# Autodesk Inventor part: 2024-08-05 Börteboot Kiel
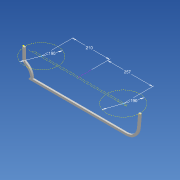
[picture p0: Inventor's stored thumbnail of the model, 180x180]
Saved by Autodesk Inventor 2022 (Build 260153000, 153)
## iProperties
Created: 2024-08
Part Number: 2024-08-05 Börteboot Kiel
Material: Generisch
Document SubType Name: Modeling
Designer: i3meg
Density: 1 g/cm^3
Appearance: Vorgabe
Author: i3meg
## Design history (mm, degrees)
sketch "Skizze3"
  geometry: L1 (0, 65)-(0, 145); L2 (45, 0)-(590, 0); L3 (-177.152, 0)-(845.976, 0) reference; L4 (0, -76.111)-(0, 353.434) reference; L5 (-13.298, 65)-(13.298, 65); L6 (45, 6.802)-(45, -6.802); L7 (649.229, 70)-(679.411, 70); L8 (590, 31.664)-(590, 6.805); L9 (664.371, 70)-(670.933, 145); L10 (655, 0)-(655, 200.893); L11 (658.887, 145)-(652.325, 70); L12 (590, 12)-(57, 12); L13 (12, 77)-(12, 145); L14 (0, 145)-(12, 145); L15 (45, 0)-(35, 0); L16 (29.578, 10)-(39.495, 10); L17 (330, 0)-(330, 292.071); L18 (670.933, 145)-(658.887, 145); A1 r 10.21 centre (45.208, -0.208) between (45, 10) and (35, 0); A2 r 62.199 centre (590.268, 74.198) between (590, 12) and (652.325, 70); A3 r 74.508 centre (590, 74.508) between (590, 0) and (664.371, 70); A4 r 55.926 centre (-10.925, 10.152) between (45, 10) and (0, 65); A5 r 68.338 centre (-11.334, 12.769) between (57, 12) and (12, 77); 1 further point
  constraints: 32 end point, 10 point on circle, 9 point on line, 5 centre point, 4 midpoint, 4 vertical, 3 perpendicular, 2 horizontal, 1 collinear, 1 parallel, 1 symmetric about line, 1 tangent
  dimensions: "d7" = 145 distance of point (0, 0) L1.end; "d11" = 45 distance between parallel lines of L4 L6; "d23" = 12 distance between parallel lines of L2 L12; "d29" = 10 distance of L2.start L15.end; "d30" = 10 distance between parallel lines of L2 L16; "d31" = 330 distance between parallel lines of L4 L17; "d34" = 12 distance between parallel lines of L9 L11; "d39" = 590 distance between parallel lines of L4 L8; "d40" = 70 distance between parallel lines of L3 L7; "d41" = 85 deg angle of L3 L9; "d42" = 145 distance between parallel lines of L3 L18; "d45" = 65 distance between parallel lines of L3 L5; "d46" = 12 distance from line of L5 L13.start; "d47" = 12 horizontal distance of A1.start L12.end
extrude "Extrusion3" new body sketch "Skizze3" stored distance "d24" = 9; taper "d25" = 0 deg
fillet "Rundung1" dims "d26" = 24
fillet "Rundung2" dims "d27" = 12
sketch "Skizze4"
  geometry: L1 (670.933, 9)-(670.933, 0) reference; L2 (57, 9)-(57, 0) reference; L3 (590, 0)-(57, 0) reference; L4 (590, 9)-(590, 0) reference; L5 (57, 9)-(590, 9) reference; L6 (35, 0)-(590, 0) reference; L7 (312.5, 0)-(312.5, 81.559); C1 r 95 at (102.5, 4.5); C2 r 95 at (569.5, 4.5); 1 further point
  constraints: 2 centre point, 2 end point, 1 midpoint, 1 perpendicular
  dimensions: "d69" = 190 diameter of C1; "d70" = 210 distance from line of L7 C1.centre; "d71" = 190 diameter of C2; "d72" = 257 distance from line of L7 C2.centre
  node "Projizierte Kontur1"
node "Volumenkörper3"
